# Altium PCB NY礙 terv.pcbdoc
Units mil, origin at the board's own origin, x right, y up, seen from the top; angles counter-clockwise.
Board outline 5566.92 x 3716.53 mil, 2 copper layers (Top Layer, Bottom Layer); 91 components, 103 nets, 338 pads, 72 vias.
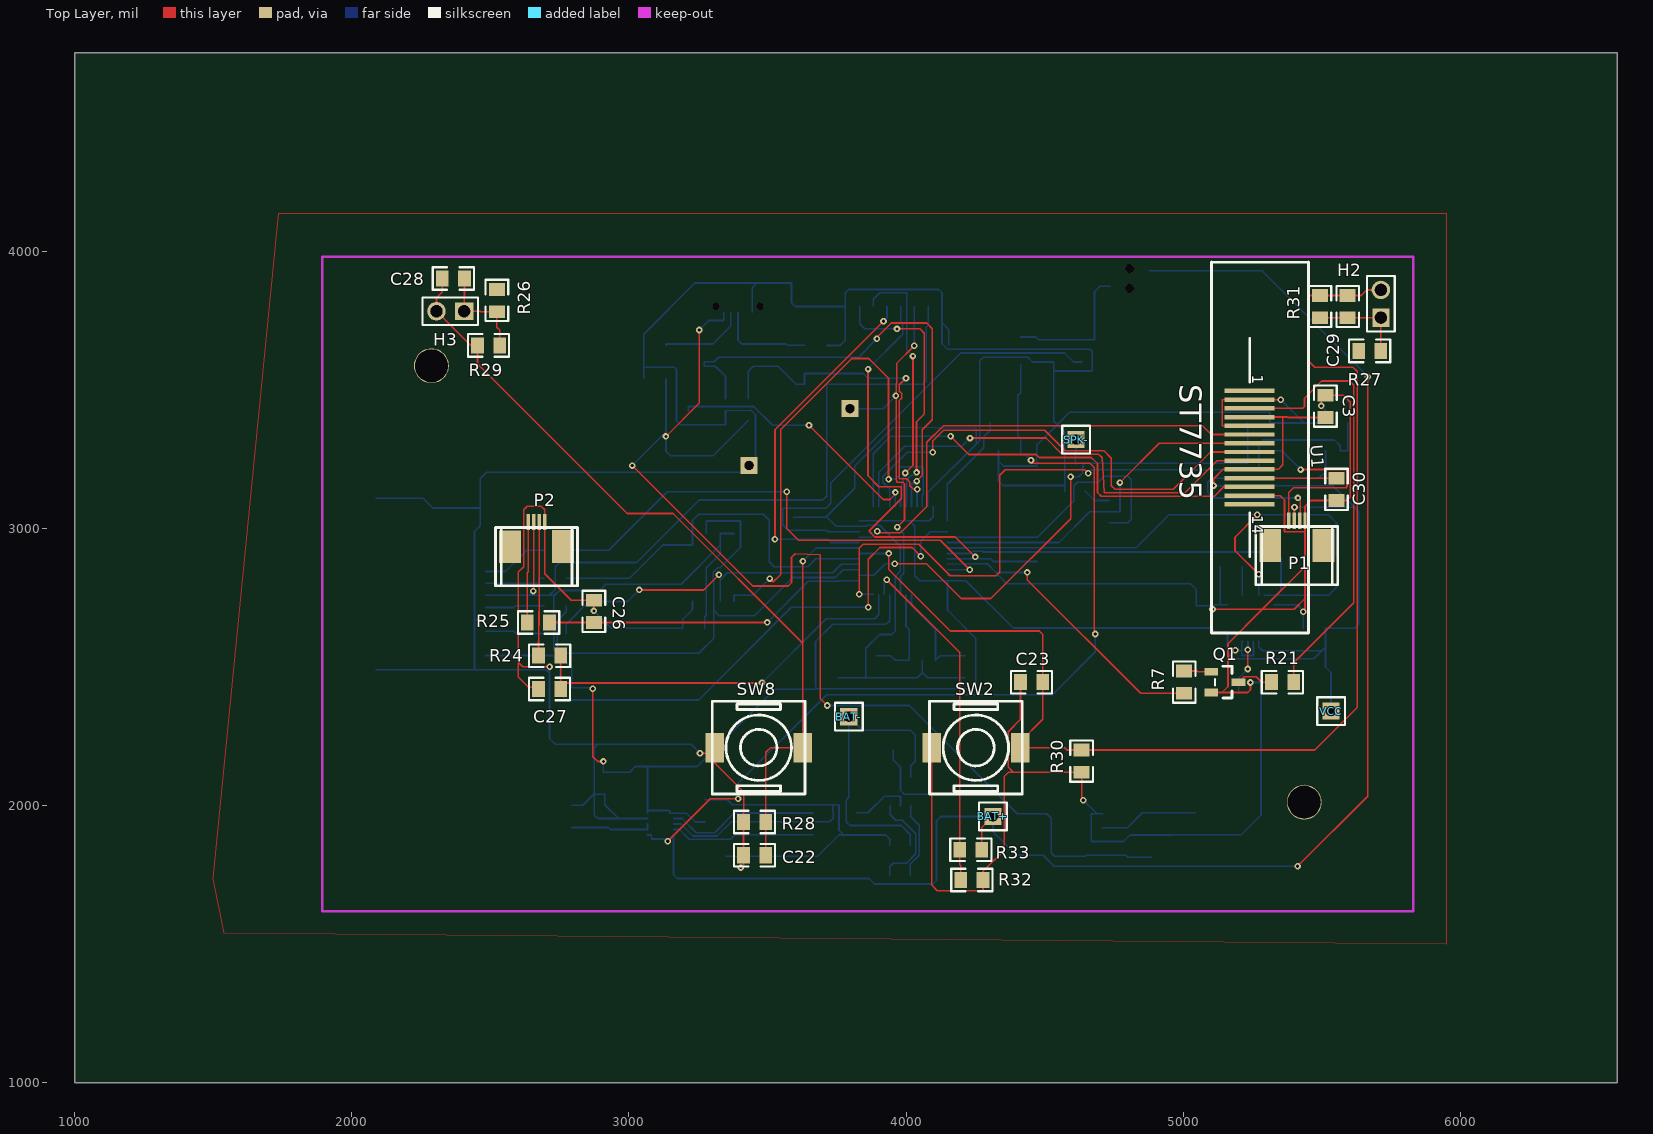
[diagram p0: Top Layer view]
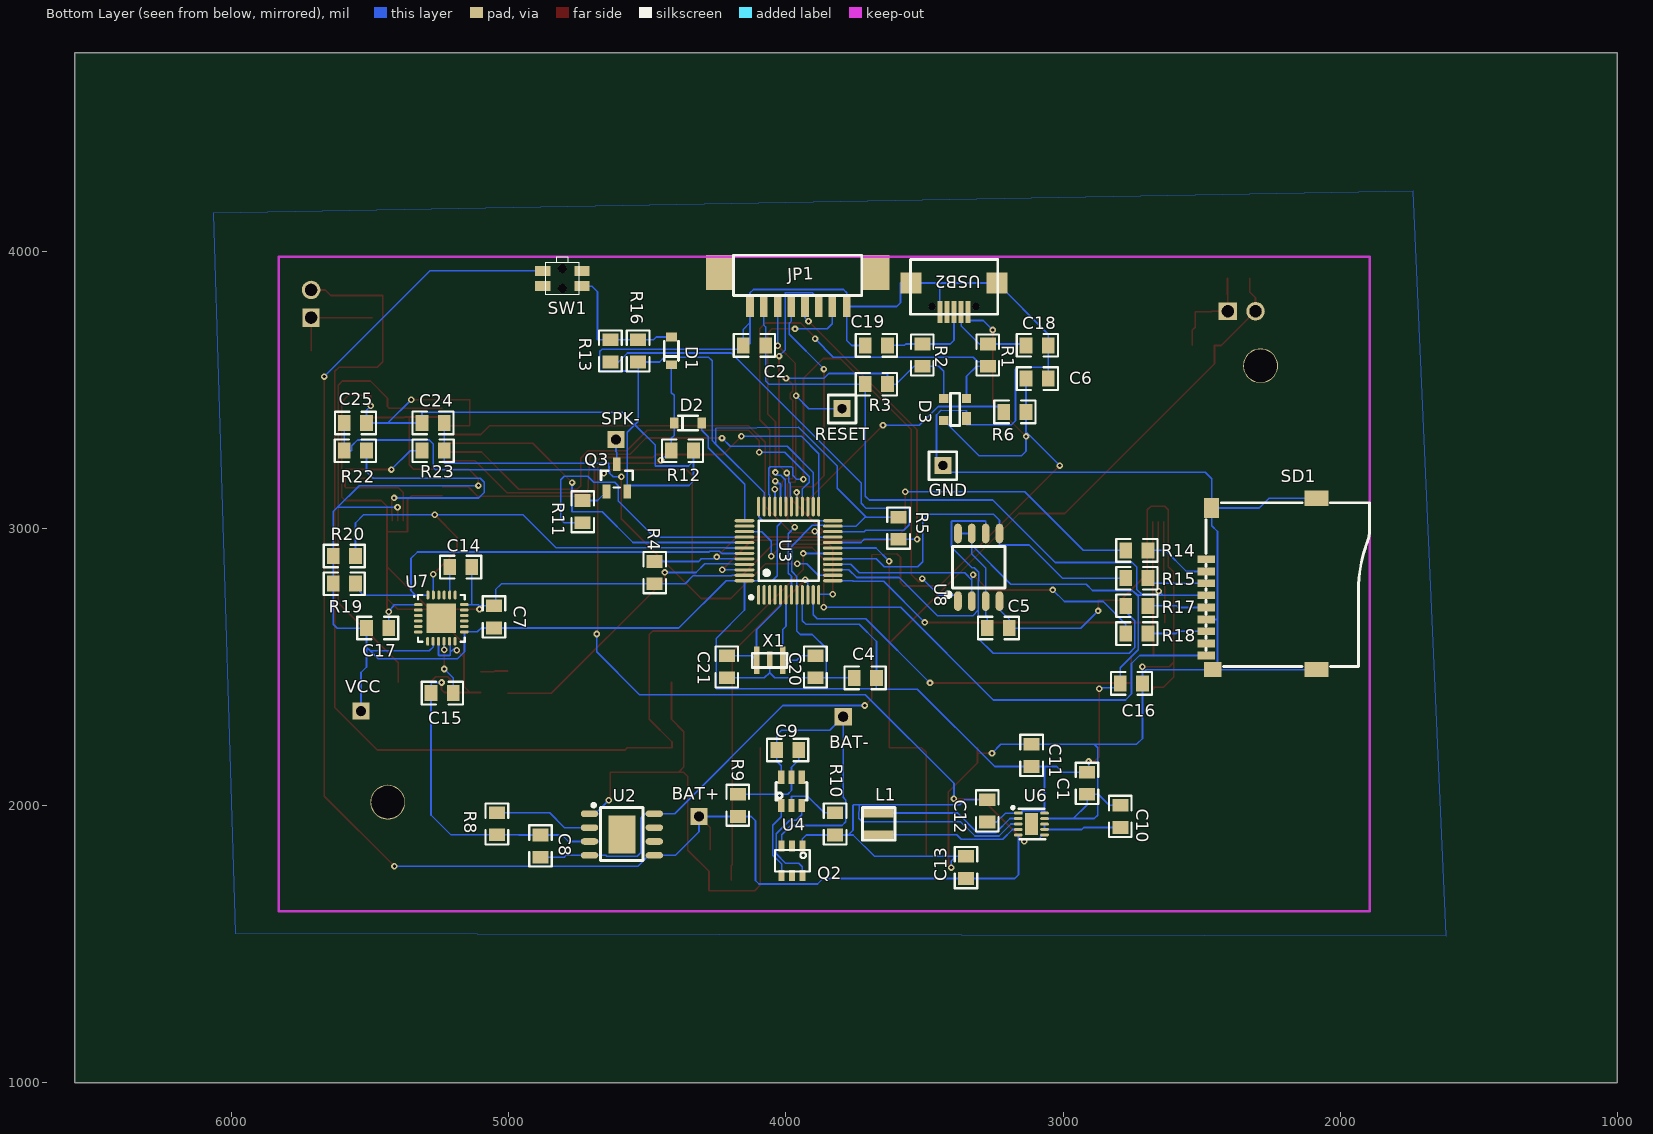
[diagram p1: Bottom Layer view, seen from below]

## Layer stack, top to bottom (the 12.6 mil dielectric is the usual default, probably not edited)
Top Layer: signal copper (thickness not stored)
Dielectric: dielectric 12.6, FR-4, Dk 4.8
Bottom Layer: signal copper (thickness not stored)

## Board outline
6566.92,1000 1000,1000 1000,4716.53 6566.92,4716.53

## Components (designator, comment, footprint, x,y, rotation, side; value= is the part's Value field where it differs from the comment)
BAT+ "Header-Male-2.54_1x1" HDR-1X1/2.54 4313.7,1960.31 r0 top
BAT- "Header-Male-2.54_1x1" HDR-1X1/2.54 3793.7,2320.31 r0 top
C1 "0.1u" 0805#1 2913.7,2040.31 r270 bottom
C2 "0.1u" 0805#1 4153.7,3660.31 r0 bottom
C3 "0.1u" 0805#2 5513.7,3480.31 r270 top
C4 "0.1u" 0805#1 3753.7,2460.31 r0 bottom
C5 "0.1u" 0805#1 3193.7,2640.31 r180 bottom
C6 "0.1u" 0805#3 3053.7,3540.31 r180 bottom
C7 "0.1u" 0805#1 5053.7,2720.31 r90 bottom
C8 "10u" 0805#1 4885.9,1893.64 r90 bottom
C9 "1u" 0805#3 4033.7,2200.31 r0 bottom
C10 "0.1u" 0805#4 2793.7,2000.31 r90 bottom
C11 "10u" 0805#1 3113.7,2220.31 r90 bottom
C12 "10u" 0805#1 3273.7,2020.31 r90 bottom
C13 "10u 10v" 0805#1 3350.4,1736.21 r270 bottom
C14 "2.2n x7r  50v" 0805#5 5213.7,2860.31 r0 bottom
C15 "0.1u x7r" 0805#1 5200.86,2405.45 r180 bottom
C16 "0.1u" 0805#1 2713.7,2440.31 r180 bottom
C17 "0.1u" 0805#1 5433.7,2640.31 r180 bottom
C18 "22p" 0805#1 3053.7,3660.31 r180 bottom
C19 "22p" 0805#3 3713.7,3660.31 r0 bottom
C20 "22p" 0805#4 3893.7,2460.31 r270 bottom
C21 "22p" 0805#1 4213.7,2460.31 r270 bottom
C22 "100n" 0805#2 3413.7,1940.31 r0 top
C23 "100n" 0805#6 4413.46,2444.82 r0 top
C24 "1u" 0805#3 5313.7,3380.31 r0 bottom
C25 "1u" 0805#3 5513.7,3380.31 r180 bottom
C26 "1u" 0805#6 2873.7,2740.31 r270 top
C27 "1u" 0805#6 2673.7,2420.31 r0 top
C28 "100n" 0805#2 2326.77,3901.57 r0 top
C29 "100n" 0805#6 5593.7,3840.31 r270 top
C30 "0.1u" 0805#2 5553.7,3180.31 r270 top
D1 "BAS70WS" SOD-323#1 4413.7,3640.31 r90 bottom
D2 "BAS70WS" SOD-323#2 4353.7,3380.31 r180 bottom
D3 "PSR05" SOT-143 3389.76,3429.13 r270 bottom
H2 "Header-Male-2.54_1x2" HDR-2X1/2.54 5713.7,3760.31 r180 top
H3 "Header-Male-2.54_1x2" HDR-2X1/2.54 2405.59,3783.4 r270 top
JP1 "1.25T-8PWT" 1.25T-8PWT 3980.39,3901.51 r0 bottom
L1 "1.5uH" 3.0*3.0*1.5MM 3665.35,1893.7 r270 bottom
P1 "FPC 0.5MM 4P" FPC-0.5MM-LSSJ-H2.0-4P 5440.94,2826.77 r0 top
P2 "FPC 0.5MM 4P" FPC-0.5MM-LSSJ-H2.0-4P 2696.93,2822.78 r0 top
Q1 "MMBTA06 1GM" SOT-23(SOT-23-3)#1 5200.65,2444.79 r270 top
Q3 "MMBTA06 1GM" SOT-23(SOT-23-3)#2 4610.31,3232.22 r0 bottom
R1 "22R" 0805#3 3271.65,3665.35 r90 bottom
R2 "22R" 0805#4 3507.87,3665.35 r90 bottom
R3 "1.5k" 0805#3 3713.7,3520.31 r0 bottom
R4 "10k" 0805#1 4473.7,2800.31 r270 bottom
R5 "10k" 0805#1 3593.7,3040.31 r90 bottom
R6 "10k" 0805#1 3213.7,3420.31 r0 bottom
R7 "1k" 0805#7 5003.74,2405.34 r90 top
R8 "2k" 0805#4 5043.38,1893.64 r270 bottom
R9 "100R" 0805#3 4173.7,2040.31 r90 bottom
R10 "2k" 0805#1 3822.91,1893.64 r270 bottom
R11 "1k" 0805#4 4733.7,3020.31 r270 bottom
R12 "10k" 0805#1 4333.7,3280.31 r180 bottom
R13 "1k" 0805#3 4633.7,3600.31 r270 bottom
R14 "1k" 0805#1 2773.7,2920.31 r0 bottom
R15 "1k" 0805#1 2773.7,2820.31 r0 bottom
R16 "10k" 0805#1 4533.7,3600.31 r270 bottom
R17 "1k" 0805#4 2773.7,2720.31 r0 bottom
R18 "1k" 0805#1 2773.7,2620.31 r0 bottom
R19 "1k5" 0805#1 5633.7,2800.31 r0 bottom
R20 "1k5" 0805#1 5633.7,2900.31 r0 bottom
R21 "100R" 0805#2 5318.7,2444.71 r0 top
R22 "1k" 0805#3 5593.7,3280.31 r0 bottom
R23 "1k" 0805#3 5233.7,3280.31 r180 bottom
R24 "1k" 0805#6 2753.7,2540.31 r180 top
R25 "1k" 0805#6 2713.7,2660.31 r180 top
R26 "1k" 0805#6 2523.7,3862.14 r270 top
R27 "1k" 0805#2 5633.7,3640.31 r0 top
R28 "10k" 0805#2 3413.7,1820.31 r0 top
R29 "10k" 0805#2 2453.7,3660.31 r0 top
R30 "10k" 0805#2 4633.7,2120.31 r90 top
R31 "10k" 0805#2 5493.7,3840.31 r270 top
R32 "10k" 0805#8 4233.7,1840.31 r180 top
R33 "20k" 0805#8 4237.9,1730.91 r0 top
SD1 "ST-TF-003A" MICRO-SD9+4P-SMD-16.1X14.5X1.85MM 2484.17,2799.27 r0 bottom
SPK- "Header-Male-2.54_1x1" HDR-1X1/2.54 4613.7,3320.31 r0 top
SW1 "SKSCLDE010" SKSCLDE010 4807.08,3901.57 r180 bottom
SW2 "SKSTAAE010" SW-SMD-8.5X8.5X3.95 4252.04,2208.66 r180 top
SW8 "SKSTAAE010" SW-SMD-8.5X8.5X3.95 3468.5,2208.66 r180 top
U1 "ST7735" "ST7735 14PIN SHORT OUTLINE" 5291.3,3291.31 r270 top
U2 "TP4056" SOP-8_EP_150MIL 4492.12,1814.96 r0 bottom
U3 "STM32F103C8T6" LQFP-48_7X7X05P 4098.5,2759.78 r270 bottom
U4 "FS312F-G" SOT23-6 3980.31,2051.18 r0 bottom
U6 "TPS63031DSKR" SON-10_3X3X05P 3114.25,1933.01 r0 bottom
U7 "MPU-6050" QFN-24_4X4X05P 5318.97,2720.41 r0 bottom
U8 "23LC1024-I/SN" SOP-8_150MIL 3229.5,2959.51 r270 bottom
USB2 "micro 5P" MICRO-USB-3 3393.7,3780.31 r270 bottom
VCC "Header-Male-2.54_1x1" HDR-1X1/2.54 5533.7,2340.31 r0 top
X1 "8MHz" 3213 4059.13,2523.56 r0 bottom

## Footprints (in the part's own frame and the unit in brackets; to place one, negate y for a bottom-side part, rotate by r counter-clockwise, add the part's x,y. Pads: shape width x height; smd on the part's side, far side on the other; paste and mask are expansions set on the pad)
1.25T-8PWT [mm]
  rect 2.4x3.2 smd: 0(-7.777,-0.552) 0(6.633,-0.551)
  rect 0.7x2 smd: 1(3.791,2.537) 2(2.542,2.537) 3(1.25,2.539) 4(0.002,2.54) 5(-1.246,2.54) 6(-2.5,2.541) 7(-3.748,2.541) 8(-5.078,2.541)
  silkscreen extent -6.45,-2.14 5.3,1.55
3.0*3.0*1.5MM [mil]
  rect 31.5x106.3 smd: 1(-0.15,0.01) 2(-78.85,0.01)
  silkscreen extent -99,-59 20,59
0805#1 [mm]
  rect 1.16x1.47 smd: 1(-0.001,0.001) 2(-2.033,0.001)
  silkscreen extent -2.89,-1.03 0.88,1.04
0805#2 [mm]
  rect 1.16x1.47 smd: 1(0.001,-0.001) 2(2.033,-0.001)
  silkscreen extent -0.88,-1.04 2.89,1.03
0805#3 [mm]
  rect 1.16x1.47 smd: 1(0.001,0.001) 2(-2.031,0.001)
  silkscreen extent -2.89,-1.03 0.88,1.04
0805#4 [mm]
  rect 1.16x1.47 smd: 1(-0.001,-0.001) 2(-2.033,-0.001)
  silkscreen extent -2.89,-1.03 0.88,1.04
0805#5 [mm]
  rect 1.16x1.47 smd: 1(0,-0.001) 2(-2.032,-0.001)
  silkscreen extent -2.89,-1.03 0.88,1.04
0805#6 [mm]
  rect 1.16x1.47 smd: 1(-0.001,0) 2(2.031,0)
  silkscreen extent -0.88,-1.04 2.89,1.03
0805#7 [mm]
  rect 1.16x1.47 smd: 1(-0.001,0.001) 2(2.031,0.001)
  silkscreen extent -0.88,-1.04 2.89,1.03
0805#8 [mm]
  rect 1.16x1.45 smd: 1(-1.016,0) 2(1.016,0)
  silkscreen extent -1.9,-1.03 1.87,1.04
3213 [mil]
  rect 19.68x98.43 smd: 1(47.22,-0.03) 3(-47.18,-0.03)
  rect 19.68x62.99 smd: 2(0.02,-0.03)
  silkscreen extent -63,-26 63,26
FPC-0.5MM-LSSJ-H2.0-4P [mm]
  rect 0.3x1.5 smd: 1(-0.021,5.082) 2(-0.52,5.082) 3(-1.02,5.082) 4(-1.52,5.082)
  rect 2x3 smd: 5(-3.206,2.822) 6(1.655,2.828)
  silkscreen extent -4.54,-0.77 2.98,4.58
HDR-1X1/2.54 [mil]
  rect 62x62 hole 35 slot 35.2 at 90 deg: 1(0,0)
  silkscreen extent -50,-50 50,50
HDR-2X1/2.54 [mil]
  rect 62x66.93 hole 43.3 slot 43.31 at 90 deg: 1(0.01,0.02)
  round 66.93 hole 43.3 slot 43.31 at 90 deg: 2(0,-100)
  silkscreen extent -50,-150 50,50
LQFP-48_7X7X05P [mm]
  oval 1.8x0.28 smd: 1(0,0) 2(0,0.5) 3(0,1) 4(0,1.5) 5(0,2) 6(0,2.5) 7(0,3) 8(0,3.5) 9(0,4) 10(0,4.5) 11(0,5) 12(0,5.5) 25(-8.1,5.5) 26(-8.1,5) 27(-8.1,4.5) 28(-8.1,4) 29(-8.1,3.5) 30(-8.1,3) 31(-8.1,2.5) 32(-8.1,2) 33(-8.1,1.5) 34(-8.1,1) 35(-8.1,0.5) 36(-8.1,0)
  oval 0.28x1.8 smd: 13(-1.3,6.8) 14(-1.8,6.8) 15(-2.3,6.8) 16(-2.8,6.8) 17(-3.3,6.8) 18(-3.8,6.8) 19(-4.3,6.8) 20(-4.8,6.8) 21(-5.3,6.8) 22(-5.8,6.8) 23(-6.3,6.8) 24(-6.8,6.8) 37(-6.8,-1.3) 38(-6.3,-1.3) 39(-5.8,-1.3) 40(-5.3,-1.3) 41(-4.8,-1.3) 42(-4.3,-1.3) 43(-3.8,-1.3) 44(-3.3,-1.3) 45(-2.8,-1.3) 46(-2.3,-1.3) 47(-1.8,-1.3) 48(-1.3,-1.3)
  silkscreen extent -6.8,-0.85 0.38,5.5
MICRO-SD9+4P-SMD-16.1X14.5X1.85MM [mil]
  rect 63x27.6 smd: 1(0.03,-89.04) 2(0.03,-45.04) 3(0.03,-2.04) 4(0.03,40.96) 5(0.03,84.96) 6(0.03,127.96) 7(0.03,170.96) 8(0.03,214.96) 9(0.03,257.96)
  rect 63x55.1 smd: G1(-23.97,309.01)
  rect 86.6x55.1 smd: G2(-397.97,309.01) G3(-397.97,-308.99)
  rect 55.1x70.9 smd: G4(-20.02,-273.99)
  silkscreen extent -591,-293 0,298
MICRO-USB-3 [mm]
  rect 1.9x1.9 smd: 0(-2.67,-3.95) 0(-2.67,3.95)
  rect 2x0.45 smd: 1(0,1.3) 2(0,0.65) 3(0,0) 4(0,-0.65) 5(0,-1.3)
  round 0.65 hole 0.65 unplated: ""(-0.521,-1.999) ""(-0.521,1.999)
  silkscreen extent -4.83,-4 0.19,4.01
QFN-24_4X4X05P [mil]
  oval 31.5x11.02 smd: 1(8,-4) 2(8,15.7) 3(8,35.4) 4(8,55) 5(8,74.7) 6(8,94.4) 13(-158,94) 14(-158,74.3) 15(-158,54.6) 16(-158,35) 17(-158,15.3) 18(-158,-4.4)
  oval 11.02x31.5 smd: 7(-26,128) 8(-45.7,128) 9(-65.4,128) 10(-85,128) 11(-104.7,128) 12(-124.4,128) 19(-125,-39) 20(-105.3,-39) 21(-85.6,-39) 22(-66,-39) 23(-46.3,-39) 24(-26.6,-39)
  rect 105.51x105.51 smd: 25(-75.02,45.01)
  silkscreen extent -160,-40 22,130
SKSCLDE010 [mil]
  rect 55.12x35.43 smd: 1(70.83,27.59) 2(-70.87,27.59) 3(70.83,-27.51) 4(-70.87,-27.51)
  round 31.5 hole 31.5 slot 31.7 at 0 deg unplated: ""(0,-35.4) ""(0,35.4)
  silkscreen extent -59,-59 59,79
SOD-323#1 [mil]
  rect 31.5x39.37 smd: 1(49.96,0.04) 2(-50.04,0.04)
  silkscreen extent -35,-26 35,26
SOD-323#2 [mil]
  rect 31.5x39.37 smd: 1(50,-0.05) 2(-50,-0.05)
  silkscreen extent -35,-26 35,26
SON-10_3X3X05P [mil]
  rect 47.24x78.74 smd: 0(-0.02,0.03)
  oval 31.5x11.02 smd: 1(47.2,-39.4) 2(47.2,-19.7) 3(47.2,0) 4(47.2,19.7) 5(47.2,39.4) 6(-47.2,39.4) 7(-47.2,19.7) 8(-47.2,0) 9(-47.2,-19.7) 10(-47.2,-39.4)
  silkscreen extent -51,-64 72,55
SOP-8_150MIL [mil]
  oval 70.87x27.56 smd: 1(222,-150) 2(222,-100) 3(222,-50) 4(222,0) 5(-22,0) 6(-22,-50) 7(-22,-100) 8(-22,-150)
  silkscreen extent 25,-193 207,20
SOP-8_EP_150MIL [mil]
  oval 62.99x23.62 smd: 1(217,-155) 2(217,-105) 3(217,-55) 4(217,-5) 5(-17,-5) 6(-17,-55) 7(-17,-105) 8(-17,-155)
  rect 98.43x137.79 smd: 9(99.99,-80.04)
  silkscreen extent 24,-192 208,14
SOT23-6 [mil]
  rect 22.2x47.7 smd: 1(36.97,51.1) 2(-0.03,51.1) 3(-37.03,51.1) 4(-37.03,-50.9) 5(-0.03,-50.9) 6(36.97,-50.9)
  silkscreen extent -56,-32 56,32
SOT-23(SOT-23-3)#1 [mil]
  rect 27.56x49.21 smd: 1(-37.42,-99.15) 2(37.38,-99.15) 3(-0.02,-0.75)
  silkscreen extent -58,-85 57,-24
SOT-23(SOT-23-3)#2 [mil]
  rect 27.56x49.21 smd: 1(37.4,99.15) 2(-37.4,99.15) 3(0,0.75)
  silkscreen extent -58,24 58,85
SOT-143 [mil]
  rect 47x33 smd: 1(31.96,41.01)
  rect 33x33 smd: 2(-39.04,41.01) 3(-39.04,-40.99) 4(39.96,-40.99)
  silkscreen extent -58,-17 58,17
"ST7735 14PIN SHORT OUTLINE" [mil]
  rect 15.75x180 smd: 1(-204.72,-51.24) 2(-173.23,-51.14) 3(-141.73,-51.25) 4(-110.24,-51.25) 5(-78.84,-51.2) 6(-47.35,-51.09) 7(-15.85,-51.21) 8(15.64,-51.2) 9(47.15,-51.2) 10(78.64,-51.09) 11(110.13,-51.21) 12(141.63,-51.2) 13(173.23,-51.15) 14(204.72,-51.24)
  silkscreen extent -670,-189 669,161
SW-SMD-8.5X8.5X3.95 [mil]
  rect 66.93x106.3 smd: 1(-159.46,0) 2(159.44,0)
  silkscreen extent -167,-167 167,167

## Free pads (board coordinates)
  rect 21.65x39.37 smd far side: 1(3941.04,1854.24) 2(3978.44,1854.24) 3(4015.84,1854.24) 4(4015.84,1747.94) 5(3978.44,1747.94) 6(3941.04,1747.94)
  round 125.98 hole 118.1 slot 118.11 at 0 deg: 319(2287.4,3586.61) 319(5437,2011.81)
  rect 62x62 hole 32 slot 32.2 at 0 deg: 320(3797.7,3432.11) 321(3433.7,3227.11)

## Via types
v1: diameter 23.62, hole 11.82, Top Layer to Bottom Layer, 72 vias

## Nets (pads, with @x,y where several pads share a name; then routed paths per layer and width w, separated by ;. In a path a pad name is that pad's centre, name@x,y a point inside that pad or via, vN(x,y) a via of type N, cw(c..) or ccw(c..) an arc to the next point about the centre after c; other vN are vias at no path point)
+5V: C6.2 C8.2 D3.4 R6.2 U2.4 U2.8 USB2.1 | length 4345
  Top Layer w6: v1(3012.2,3226.56) 3447,2791.76 3574.5,2791.76 3587,2804.26 3587,2895.76 3600,2908.76 3691,2904.26 3691,2385.76 v1(3716,2360.76) ; v1(3133.7,3331.76) 3254,3452.06 v1(3254,3715.76)
  Bottom Layer w6: v1(3012.2,3226.56) 3133.7,3348.06 ; 3133.7,3503.76 R6.2 3133.7,3348.06 ; 3133.68,3503.78 C6.2 ; v1(3254,3715.76) 3288,3749.76 3342.5,3749.76 USB2.1 ; D3.4 3303.34,3261.76 3150,3261.76 3133.7,3278.06 v1(3133.7,3331.76) 3133.7,3348.06 ; v1(3716,2360.76) 4011.2,2360.76 4402,1969.96 U2.8 4508.3,1969.96 4524,1954.26 4524,1829.26 4536.5,1816.76 4646.8,1816.76 4650,1819.96 U2.4 4794,1819.96 4800.35,1813.61 C8.2
BAT+: BAT+.1 C13.1 R9.2 R32.1 SW1.2 U2.5 U6.5 | length 5698.3
  Top Layer w6: R32.1 4273.7,1920.31 BAT+.1 ; v1(5413,1780.76) 5666,2033.76 v1(5666,3547.76)
  Bottom Layer w6: U6.5 3161,1893.61 3161,1750.22 3175,1736.22 C13.1 3866.54,1736.22 3886,1716.76 4097.5,1716.76 4110,1729.26 4110,1945.3 4125,1960.3 R9.2 4243,1960.3 BAT+.1 4313.7,1905.06 4398.8,1819.96 U2.5 4495,1819.96 4534.2,1780.76 v1(5413,1780.76) ; SW1.2 5284.6,3929.16 v1(5666,3547.76)
BAT-: BAT-.1 C9.1 pad.3 U4.6 | length 1100.8
  Bottom Layer w6: pad.3 4015.84,1894.76 3982.84,1927.76 3798,1927.76 3784,1941.76 3784,2019.76 3793.7,2029.46 BAT-.1 3842.25,2271.76 4016.21,2271.76 4033.71,2254.26 C9.1 4033.71,2159.19 4017.28,2142.76 U4.6
BATT: R32.2 R33.1 U3.10 | length 1253.4
  Top Layer w6: v1(3930.67,2814.75) 4193.7,2551.72 R32.2 4193.7,1786.96 4197.9,1782.76 R33.1
  Bottom Layer w6: U3.10 3921.33,2805.41 v1(3930.67,2814.75)
BOOT0: JP1.4 R4.2 U3.44 | length 1770.4
  Top Layer w6: v1(3863,3574.76) 3863,3189.57 3902,3150.57 3981,3150.57 3982.81,3148.76 3982.81,3107.26 3867,2991.45 3867,2989.45 3887.5,2968.95 4177.81,2968.95 v1(4250,2896.76)
  Bottom Layer w6: v1(3863,3574.76) 3988.31,3700.07 3988.31,3740.57 3980.45,3748.43 JP1.4 ; U3.44 v1@4242.94,2889.7 ; v1(4250,2896.76) v1@4242.94,2889.7 ; R4.2 4315.39,2880.31 4306,2889.7 v1@4242.94,2889.7
BOOT1: JP1.5 R5.2 U3.20 | length 1317.3
  Top Layer w6: v1(3527,2960.31) 3527,3355.41 v1(3918.85,3747.26)
  Bottom Layer w6: v1(3527,2960.31) R5.2 3718,2960.31 3729.55,2948.76 U3.20 ; v1(3918.85,3747.26) 3931.35,3759.76 JP1.5
BTN1: C23.2 C29.1 H2.2 R30.2 R31.1 SW2.1 U3.18 | length 4449
  Top Layer w6: v1(3938.03,2909.39) 3938.03,2851.76 4160.03,2629.76 4480.44,2629.76 4493.44,2616.76 C23.2 4493.44,2310.7 4411.5,2228.76 SW2.1 4411.5,2208.07 4572.33,2208.07 4580.07,2200.32 R30.2 5474.56,2200.32 5628,2353.76 5628,3566.76 5613,3581.76 5475,3581.76 5455,3601.76 5455,3839.3 5456,3840.3 R31.1 5543,3840.3 ; 5543.03,3840.33 C29.1 5643,3840.33 5662.98,3860.31 H2.2
  Bottom Layer w6: U3.18 v1(3938.03,2909.39)
BTN2: C22.2 C28.1 H3.2 R28.2 R29.1 SW8.1 U3.19 | length 3393.2
  Top Layer w6: C28.1 2326.81,3852.98 2305.59,3831.76 H3.2 2429.23,3659.76 R29.1@2453.71,3659.76 ; R29.1 R29.1@2453.71,3659.76 ; R28.2 3493.71,1879.76 ; 3493.74,1879.79 C22.2 3493.74,2191.76 3510.74,2208.76 SW8.1@3627.95,2208.76 ; SW8.1 SW8.1@3627.95,2208.76 ; v1(3627.95,2881.71) 3627.95,2584.81 ; R29.1@2453.71,3659.76 2453.71,3593.76 2993.71,3053.76 3159,3053.76 3627.95,2584.81 ; SW8.1@3627.95,2208.76 3627.95,2584.81
  Bottom Layer w6: v1(3627.95,2881.71) 3675.31,2929.07 U3.19
C10_2: C10.2 U6.7 U6.8 | length 296
  Bottom Layer w6: C10.2 2926,1920.27 2932.96,1913.31 U6.7 U6.8
C28_2: C28.2 H3.1 R26.2 R29.2 | length 363.3
  Top Layer w6: C28.2 2406.81,3842.97 2405.6,3841.76 H3.1 2464,3783.41 2465.26,3782.15 R26.2 2523.69,3725.78 2533.71,3715.76 R29.2
C29_2: C29.2 H2.1 R27.2 R31.2 | length 340
  Top Layer w6: R31.2 5543,3760.3 ; 5543.03,3760.33 C29.2 5653,3760.33 5653.04,3760.29 H2.1 5713.69,3699.79 ; R27.2 5713.72,3699.76
CPOUT: C14.1 U7.20 | length 100.9
  Bottom Layer w6: U7.20 5213.67,2810.41 5213.71,2810.45 C14.1
D+: D3.3 R2.2 R3.2 U3.33 | length 1276.5
  Top Layer w6: v1(4000.01,3541.76) 3976.19,3517.93 3976.19,3495.06 3984.51,3486.73 3984.51,3469.49 3976.19,3461.17 3976.19,3180.76 3978,3178.95 4002.44,3178.95 4013.82,3167.56 4013.82,3154.26 4027.32,3140.76 v1(4040.62,3140.76)
  Bottom Layer w6: D3.3 3430.75,3566.76 3449.3,3585.31 R2.2 3538,3585.31 3603.04,3520.27 R3.2 3633.71,3557.76 3634.71,3558.76 3846,3558.76 3863,3541.76 v1(4000.01,3541.76) ; U3.33 4039.44,3139.58 v1(4040.62,3140.76)
D-: D3.2 R1.2 U3.32 | length 1764.6
  Top Layer w6: v1(3895,3683.76) 3895,3688.76 3947,3740.76 4075,3740.76 4095,3720.76 4095,3391.76 4059,3355.76 4059,3190.76 v1(4039,3170.76)
  Bottom Layer w6: D3.2 3348.75,3548.62 3312,3585.37 R1.2 3271.65,3601.76 3308,3601.76 3324,3617.76 3829,3617.76 v1(3895,3683.76) ; U3.32 4019.76,3160.76 4020.76,3161.76 4038,3161.76 4039,3162.76 v1(4039,3170.76)
D_BR: R7.1 U3.45 | length 1063.5
  Top Layer w6: v1(4438,2840.76) 4438,2813.88 4846.57,2405.31 R7.1
  Bottom Layer w6: U3.45 4205.74,2872.76 4293,2872.76 4325,2840.76 v1(4438,2840.76)
D_CS: U1.12 U3.25 | length 1740
  Top Layer w6: v1(4160.7,3332.06) 4226.19,3266.57 4470.13,3266.57 4480.95,3255.76 4669,3255.76 4690.81,3233.95 4690.81,3129.26 4704.31,3115.76 5113.12,3115.76 5147.05,3149.68 U1.12
  Bottom Layer w6: U3.25 3881.96,3269.72 3944.3,3332.06 v1(4160.7,3332.06)
D_DC: U1.7 U3.41 | length 1299.7
  Top Layer w6: v1(4772,3165.26) 4913.9,3307.16 U1.7
  Bottom Layer w6: U3.41 4552,2948.76 4663,3059.76 4772,3060.76 v1(4772,3165.26)
D_RS: U1.6 U3.21 | length 1730.1
  Top Layer w6: v1(3896.5,2989.76) 3902.31,2983.95 3980.19,2983.95 4074.81,3078.57 4074.81,3310.57 4135,3370.76 5070,3370.76 5102.1,3338.66 U1.6
  Bottom Layer w6: U3.21 3875.18,2968.44 v1(3896.5,2989.76)
GND: C1.1 C2.1 C3.1 C4.1 C5.1 C6.1 C7.1 C8.1 C10.1 C11.1 C12.1 C13.2 C14.2 C15.2 C16.1 C17.1 C18.1 C19.1 C20.1 C21.1 C22.1 C23.1 C24.1 C25.1 C26.1 C27.1 C30.2 D3.1 JP1.1 JP1.8 P1.1 P2.1 pad.1 pad.321 Q1.2 Q3.2 R4.1 R5.1 R8.1 R10.1 R12.1 R16.1 R28.1 R30.1 R33.2 SD1.6 SD1.G1 SD1.G2 SD1.G3 SD1.G4 SW2.2 SW8.2 U1.2 U1.5 U1.13 U2.1 U2.3 U3.8 U3.23 U3.35 U3.47 U6.3 U6.9 U7.1 U7.9 U7.11 U7.18 U8.4 USB2.0 USB2.5 X1.2 | length 25650.5
  Top Layer w6: C27.1 2673.68,2426.76 2637.5,2426.76 2601,2463.26 2601,2516.76 ; v1(2713.7,2500.76) 2617,2500.76 2601,2516.76 ; v1(2873.7,2702.06) C26.1 2791.53,2740.33 2696.1,2835.76 P2.1 2696.1,3066.76 2683.1,3079.76 2633,3079.76 2620,3066.76 2620,2861.76 2601,2842.76 2601,2516.76 ; v1(3256.55,2188.76) SW8.2@3309.05,2188.76 ; SW8.2 SW8.2@3309.05,2188.76 ; v1(3404,1775.76) 3413.71,1785.47 R28.1 3413.71,1879.76 ; 3413.74,1879.79 C22.1 3414.81,2004.02 3414.81,2048.69 3309.05,2154.45 SW8.2@3309.05,2188.76 ; SW2.2 4092.6,1712.66 4112.5,1692.76 4276.9,1692.76 4277.9,1693.76 R33.2 4277.9,1762.66 4354,1838.76 4354,2104.26 4370.06,2120.32 4387.5,2120.32 ; C23.1 4413.44,2310.76 4369,2266.32 4369,2138.82 4387.5,2120.32 ; v1(4640,2018.96) 4633.71,2025.25 R30.1 4387.5,2120.32 ; Q1.2 5140.15,2407.41 ; v1(5106,2707.76) 5286.1,2707.76 ; v1(5188,2559.76) 5162,2533.76 ; U1.5 5142,3370.15 5141,3371.15 5141,3463.54 5142,3464.54 U1.2 v1(5352.72,3464.54) ; U1.13 5350.18,3118.08 5366,3102.26 5366,2988.76 5367,2987.76 5439.1,2987.76 5440.1,2988.76 ; v1(5243,2443.76) 5243,2417.41 5233,2407.41 5140.15,2407.41 ; v1(5433.71,2698.76) 5440.1,2705.15 5440.1,2746.86 ; v1(5498,3441.76) 5498,3480.27 C3.1 5578.49,3480.27 5603.63,3455.13 5603.63,3112.93 5591,3100.3 C30.2 5461.14,3100.3 5440.1,3079.26 P1.1 5440.1,2988.76 ; 5140.15,2407.41 5162,2429.26 5162,2533.76 ; 5162,2533.76 5162,2583.66 5286.1,2707.76 ; 5286.1,2707.76 5440.1,2861.76 ; 5286.1,2707.76 5401,2707.76 5440.1,2746.86 ; 5440.1,2746.86 5440.1,2861.76 ; 5440.1,2861.76 5440.1,2988.76
  Bottom Layer w6: SD1.G2 SD1.G1@2443,2490.26 ; SD1.G3 2257,3108.26 2292,3073.26 SD1.G4 ; SD1.6 2444,2671.31 ; v1(2713.7,2500.76) 2713.7,2476.56 ; C10.1 2833,2000.27 2873.08,2040.35 2875,2040.35 ; v1(2873.7,2702.06) 2936,2639.76 3193.74,2639.76 C5.1 3193.74,2670.76 3229.5,2706.52 U8.4 ; C1.1 C1.1@2913,2040.35 ; C6.1 3053.68,3579.76 ; U6.9 2963,1952.71 ; U6.3@3161.45,1933.06 3187.92,1933.06 3231.18,1889.76 3318,1889.76 3370,1941.76 3724.5,1941.76 3737,1954.26 3736,2002.76 ; v1(3256.55,2188.76) 3225,2220.31 C11.1 2887.5,2220.31 ; C12.1 3355.37,2020.31 3372.9,2002.79 3736,2002.79 3755.97,2002.79 3758,2000.76 3758,1910.64 3775,1893.64 ; C13.2 3387.5,1816.22 ; v1(3404,1775.76) 3404,1799.72 3387.5,1816.22 ; USB2.5 3444.9,3867.83 3462.5,3885.43 ; R5.1 3710.55,3040.31 ; C19.1 3713.71,3659.76 3762.5,3659.76 3780.45,3677.71 JP1.8@3780.45,3800.76 ; C4.1 3823,2460.27 3823.06,2460.33 C20.1 ; pad.1 3941.04,1879.26 3926.66,1893.64 R10.1 3775,1893.64 ; X1.2 4059.15,2479.26 ; U3.35 4078.81,3129.5 4252.95,3303.64 ; U3.47 4195.11,2830.65 4197,2828.76 4335.55,2828.76 4364,2800.31 R4.1 5026.95,2800.31 5048,2779.26 5048,2720.27 C7.1 5093.49,2720.27 ; C2.1 4153.66,3718.76 4129.65,3742.77 ; C21.1 4078.08,2460.33 4059.15,2479.26 ; R12.1 4333.7,3242.76 ; Q3.2 Q3.2@4572.91,3154.76 ; v1(4640,2018.96) U2.1@4689,1969.96 ; U2.1 U2.1@4689,1969.96 ; v1(5106,2707.76) 5093.49,2720.27 ; C14.2 5133.71,2726.1 5135,2724.81 ; U7.18 5135,2724.81 ; v1(5188,2559.76) 5195,2566.76 5211.95,2553.78 ; U7.11 5214.27,2591.9 5211.95,2591.9 5211.95,2553.78 ; v1(5243,2443.76) 5279.86,2443.76 C15.2 5280.86,1965.53 5209,1893.67 R8.1 4964.06,1893.67 4964,1893.61 C8.1 4808.65,1893.61 4785,1869.96 U2.3 4669,1869.96 4668,1870.96 4668,1968.96 4669,1969.96 U2.1@4689,1969.96 ; U7.9 5253.57,2582.67 5253.81,2582.42 5253.81,2542.76 5252,2540.95 5213,2540.95 5211.95,2542 5211.95,2553.78 ; U7.1 5413.56,2724.41 v1(5433.71,2698.76) C17.1 ; v1(5352.72,3464.54) 5436.95,3380.31 ; v1(5498,3441.76) 5513.68,3426.08 C25.1 5436.95,3380.31 ; SD1.G1@2443,2490.26 SD1.G1 2700,2490.26 2713.7,2476.56 ; SD1.G1@2443,2490.26 2443,2670.31 2444,2671.31 ; 2444,2671.31 2443,2672.31 2443,2988.76 2464.15,3009.91 SD1.G4 ; SD1.G4 2464.15,3179.41 2487.5,3202.76 3416,3202.76 3457,3243.76 3457,3409.26 3440.5,3425.76 3348.75,3424.76 D3.1 3348.75,3373.26 3187.5,3373.26 3172,3388.76 3172,3573.76 3165,3580.76 3054.68,3580.76 3053.68,3579.76 ; 2713.7,2476.56 C16.1 2713.7,2241.76 2735.15,2220.31 2887.5,2220.31 ; 2875,2040.35 C1.1@2913,2040.35 ; 2875,2040.35 2875,2207.81 2887.5,2220.31 ; 2875,2040.35 2875,1965.21 2887.5,1952.71 2963,1952.71 ; C1.1@2913,2040.35 2913,2002.71 2963,1952.71 ; 3053.68,3579.76 3053.68,3599.76 C18.1 3053.69,3700.93 3238.19,3885.43 3462.5,3885.43 ; 3387.5,1816.22 3680.46,1816.22 3757.88,1893.64 3775,1893.64 ; 3462.5,3885.43 3549.21,3885.43 3587,3885.43 3587,3813.76 3600,3800.76 JP1.8@3780.45,3800.76 ; 3710.55,3040.31 3715,3040.31 3747.5,3007.81 U3.23 3857.07,3007.81 3860.13,3010.87 3904.84,3010.87 3979.81,2935.9 3979.81,2845.58 3960.7,2826.47 U3.8 3960.7,2629.26 3948.2,2616.76 3905,2616.76 3855,2566.76 3855,2461.33 C20.1 ; 3710.55,3040.31 3815,3144.76 3815,3224.76 3955,3364.76 4252.95,3361.81 4252.95,3303.64 ; JP1.8@3780.45,3800.76 JP1.8 3780.45,3849.76 3792.57,3861.88 4117.53,3861.88 4129.65,3849.76 JP1.1 4129.65,3742.77 ; C20.1 4040.22,2460.33 4059.15,2479.26 ; 4129.65,3742.77 4129.65,3666.76 4149.65,3646.76 4664,3646.76 4672,3638.76 4672,3568.76 4671,3567.76 4534.65,3567.76 4533.65,3568.76 ; 4252.95,3303.64 4266,3316.69 4266.07,3604.26 4279.57,3617.76 4439,3617.76 4456.46,3600.3 R16.1 4533.65,3568.76 ; 4333.7,3242.76 4351.75,3224.71 4471.11,3224.71 4472.16,3225.76 4472.16,3300.92 4545.46,3374.22 ; 4333.7,3242.76 4333.7,3171.06 4350,3154.76 Q3.2@4572.91,3154.76 ; 4533.65,3568.76 4533.65,3386.02 4545.46,3374.22 ; 4545.46,3374.22 4590,3418.76 5312.71,3418.76 5313.71,3417.76 C24.1 5413.01,3380.31 5436.95,3380.31 ; 4545.46,3374.22 4572.91,3346.76 Q3.2@4572.91,3154.76 ; 5093.49,2720.27 5105,2720.27 5109.54,2724.81 5135,2724.81
LED-: R21.2 U1.3 | length 1602.9
  Top Layer w6: U1.3 5431.42,3433.04 5437.77,3439.39 5437.77,3469.82 5499.72,3531.76 5601,3531.76 5616,3516.76 5616,2731.76 5398.7,2514.46 R21.2
MISO1: R18.1 U3.16 U8.2 | length 1280.9
  Top Layer w6: v1(3037,2777.76) 3270,2777.76 v1(3325,2832.76)
  Bottom Layer w6: R18.1 2773.69,2654.26 2855.19,2735.76 2995,2735.76 v1(3037,2777.76) ; v1(3325,2832.76) 3329.5,2828.26 3329.5,2813.76 ; U8.2 3329.5,2813.76 ; U3.16 3766.26,2870.02 3735.81,2839.57 3355.31,2839.57 3329.5,2813.76
MISO2: U3.27
MOSI1: R15.1 U3.17 U8.5 | length 1383.6
  Bottom Layer w6: R15.1 2773.69,2819.76 3002,2819.76 3122,2939.76 3228.5,2939.76 3229.5,2940.76 U8.5 3229.5,3029.26 3251,3050.76 3484.5,3050.76 3506,3029.26 3506,2879.26 3524.36,2860.9 3645,2860.9 3673.81,2889.7 U3.17
MOSI2: U1.8 U3.28 | length 1737.2
  Top Layer w6: v1(4097,3274.76) 4097,3315.49 4135.27,3353.76 4500.7,3353.76 4574.7,3279.76 4714.19,3279.76 4740.69,3253.26 4740.69,3154.26 4754.19,3140.76 4964.09,3140.76 5099,3275.67 U1.8
  Bottom Layer w6: U3.28 3941.02,3141.76 3916.19,3166.59 3916.19,3186.37 4004.58,3274.76 v1(4097,3274.76)
OSC_IN: C21.2 U3.5 X1.1 | length 386.3
  Bottom Layer w6: U3.5 4019.76,2721 4106.35,2634.41 X1.1 4123.09,2540.33 C21.2
OSC_OUT: C20.2 U3.6 X1.3 | length 366.3
  Bottom Layer w6: C20.2 3944,2540.33 3960.74,2523.59 X1.3 4011.95,2634.76 4000.07,2646.64 U3.6
P1_2: P1.2 R22.2 | length 976
  Top Layer w6: v1(5414.5,3109.76) 5422.81,3101.45 5422.81,3052.67 5420.45,3052.67 P1.2
  Bottom Layer w6: v1(5414.5,3109.76) 5108.5,3109.76 5089,3129.26 5089,3166.76 5103,3180.76 5490,3180.76 5513.72,3204.48 R22.2
P1_4: P1.4 R23.2 | length 689.5
  Top Layer w6: P1.4 5381.1,3129.26 5398.6,3146.76 5588.63,3146.76 5591.63,3149.76 5591.63,3210.76 5590.25,3212.14 v1(5424,3212.14)
  Bottom Layer w6: R23.2 5313.68,3279.76 5356.38,3279.76 v1(5424,3212.14)
P2_2: P2.2 R24.2 | length 482.6
  Top Layer w6: R24.2 2676.45,2755.68 P2.2
P2_4: P2.4 R25.2 | length 364
  Top Layer w6: R25.2 2633.72,2839.76 2637.1,2843.14 P2.4
PS_BTN: D1.1 R13.2 R16.2 SW1.3 | length 508.2
  Bottom Layer w6: D1.1 4468,3690.27 4477.97,3680.3 R16.2 4583,3680.3 R13.2 4679,3680.31 4680,3681.31 4680,3854.26 4699.8,3874.06 SW1.3
PS_EN: D1.2 D2.2 R12.2 U6.6 | length 3239
  Top Layer w6: v1(3140,1870.76) 3293,2023.76 v1(3394,2023.76) ; v1(4451,3245.76) 4451,3235.76 4663.81,3234.76 4678.81,3219.76 4678.81,2622.95 v1(4683,2618.76)
  Bottom Layer w6: U6.6 3081,1893.61 3082,1878.76 3132,1878.76 v1(3140,1870.76) ; v1(3394,2023.76) 3394,2080.26 3713.5,2399.76 4528.5,2399.76 4683,2554.26 v1(4683,2618.76) ; D1.2 4413.74,3489.8 4403.7,3479.76 D2.2 4403.7,3334.76 4413.7,3324.76 R12.2 4413.7,3265.76 4431,3265.76 v1(4451,3245.76)
PS_ENB: D2.1 U3.37 | length 417.5
  Bottom Layer w6: U3.37 4149,3027.5 4149,3159.41 4280.34,3290.75 4280.34,3330.27 4303.7,3353.63 D2.1
Q1_1: Q1.1 R7.2 | length 99.1
  Top Layer w6: R7.2 5051,2485.31 5054.1,2482.21 Q1.1
Q1_3: Q1.3 R21.1 | length 135.2
  Top Layer w6: Q1.3 5200.86,2444.81 5220.62,2464.57 5263.81,2464.57 5283.67,2444.71 R21.1
Q2_2: pad.2
Q2_5: pad.5
Q3_1: Q3.1 R11.2 | length 99.6
  Bottom Layer w6: Q3.1 4680.43,3100.35 R11.2
R26_1: R26.1
R27_1: R27.1
RAM_CS: U3.34 U8.1 | length 1945.6
  Top Layer w6: v1(3508,2818.76) 3508,2817.76 3519,2806.76 3521,2806.76 3548,2833.76 3548,3356.76 3804,3612.76 3866,3612.76 3937,3541.76 v1(3937,3177.07)
  Bottom Layer w6: U8.1 3379.5,2758.76 3448,2758.76 v1(3508,2818.76) ; v1(3937,3177.07) 3962,3177.07 3976.19,3191.26 3976.19,3218.76 3980,3222.57 4056.5,3222.57 4062.31,3216.76 4062.31,3123.13 4059.13,3119.95 U3.34
REGOUT: C15.1 U7.10 | length 200.7
  Top Layer w6: v1(5233,2492.4) v1(5233,2561.76)
  Bottom Layer w6: C15.1 5200.86,2460.26 v1(5233,2492.4) ; v1(5233,2561.76) 5233.97,2562.73 U7.10
RESET: JP1.3 pad.320 U3.7 | length 1305
  Top Layer w6: v1(3968,3004.76) 3994.81,3031.57 3994.81,3159.88 3987.75,3166.95 3966,3166.95 3966,3173.98 3964.19,3175.79 3964.19,3522.9 3966,3524.72 3966,3595.16 v1(4029.6,3658.76)
  Bottom Layer w6: pad.320 3917.7,3432.11 v1(3963.7,3478.11) ; v1(3968,3004.76) 3991.81,2980.95 3991.81,2838.45 3980.39,2827.03 U3.7 ; v1(4029.6,3658.76) JP1.3
RX0: JP1.7 U3.31 | length 972.7
  Top Layer w6: v1(3967.5,3719.76) 4050.5,3719.76 4066,3704.26 4066,3412.76 4038,3384.76 v1(4038,3201.76)
  Bottom Layer w6: JP1.7 3832.85,3737.91 3851,3719.76 v1(3967.5,3719.76) ; U3.31 4003,3111.69 4003,3175.76 4018.81,3191.57 4038,3192.57 v1(4038,3201.76)
SCK1: R17.1 U3.15 U8.6 | length 2004
  Bottom Layer w6: R17.1 2773.69,2699.45 2741,2666.76 2741,2569.76 2761.86,2548.9 3252.14,2548.9 3306,2602.76 3306,2705.57 ; U8.6 3279.5,3025.76 3280.5,3026.76 3401.5,3026.76 3402.5,3025.76 3402.5,2931.26 3329.08,2857.84 3320.27,2857.84 3304.19,2841.76 3304.19,2813.76 ; U3.15 3773,2850.33 3745.03,2822.36 3591,2822.36 3453.4,2684.76 3325,2684.76 3306,2705.57 ; 3304.19,2813.76 3306,2811.95 ; 3304.19,2813.76 3304.19,2811.95 3306,2811.95 ; 3306,2705.57 3306,2811.95
SCK2: U1.9 U3.26 | length 1707.9
  Top Layer w6: v1(4231,3325.76) 4505,3325.76 4563,3267.76 4694.5,3267.76 4708,3254.26 4716,3128.76 5006.6,3128.76 5122,3244.16 U1.9
  Bottom Layer w6: U3.26 3901.65,3201.49 3995.92,3295.76 4201,3295.76 v1(4231,3325.76)
SCL: R20.2 U3.42 U7.23 | length 1942.9
  Top Layer w6: v1(5268,3048.76) 5187.5,2968.26 5187.5,2919.26 v1(5272.67,2834.09)
  Bottom Layer w6: U3.42 4216.61,2929.07 4217.24,2929.71 4829.95,2929.71 4949,3048.76 v1(5268,3048.76) 5524.4,3048.76 5553.7,3019.46 R20.2 ; U7.23 v1(5272.67,2834.09)
SD1_1: SD1.1
SD1_2: R14.2 SD1.2 | length 241.6
  Bottom Layer w6: SD1.2 2555,2844.31 2631.45,2920.76 2693.67,2920.76 R14.2
SD1_3: R15.2 SD1.3 | length 228.5
  Bottom Layer w6: SD1.3 2675.34,2801.31 2675.34,2820.31 R15.2
SD1_5: R17.2 SD1.5 | length 212
  Bottom Layer w6: SD1.5 2585,2714.31 2591.04,2720.35 R17.2
SD1_7: R18.2 SD1.7 | length 212.8
  Bottom Layer w6: SD1.7 2584,2628.31 2592.02,2620.29 R18.2
SD1_8: SD1.8
SD_CS: R14.1 U3.46 | length 1818.7
  Top Layer w6: v1(3570,3131.76) 3570,2999.26 3612.31,2956.95 4123.39,2956.95 v1(4230,2850.33)
  Bottom Layer w6: R14.1 2773.67,2920.76 2927,2920.76 3138,3131.76 v1(3570,3131.76) ; U3.46 v1(4230,2850.33)
SD_SENSE: SD1.9 U3.39 | length 2206.9
  Top Layer w6: v1(3864,2714.76) 3864,2888.76 3906,2930.76 4022,2930.76 v1(4053,2899.76)
  Bottom Layer w6: SD1.9 2724,2541.31 2753,2512.31 2753,2402.76 2775,2380.76 3252,2380.76 3586,2714.76 v1(3864,2714.76) ; v1(4053,2899.76) 4053,2953.63 4087.5,2988.13 U3.39
SDA: R19.2 U3.43 U7.24 | length 1643.5
  Bottom Layer w6: U3.43 4232,2909.39 4240.31,2917.71 4275,2917.71 4277.95,2914.76 5330,2914.76 5353,2891.76 5353,2774.26 5337.5,2758.76 ; U7.24 5292.37,2758.76 5337.5,2758.76 ; R19.2 5553.69,2787.76 5524.69,2758.76 5337.5,2758.76
SPK-: Q3.3 SPK-.1 | length 90.2
  Bottom Layer w6: Q3.3 4610.31,3273.76 4613.7,3277.15 SPK-.1
SPKR: R11.1 U3.40 | length 1017.7
  Bottom Layer w6: U3.40 4474.68,2968.44 4605,3098.76 4605,3154.26 4617.5,3166.76 4694,3166.76 4715,3187.76 4800,3187.76 4812.5,3175.26 4812.5,3032.85 4800,3020.35 R11.1
SW1_1: SW1.1
SW1_4: SW1.4
TX0: JP1.6 U3.30 | length 957.9
  Top Layer w6: v1(3997,3199.76) 4025,3227.76 v1(4025,3621.76)
  Bottom Layer w6: JP1.6 3881.95,3826.76 3905.07,3849.88 4002.11,3849.88 4003.23,3848.76 4003.23,3643.53 v1(4025,3621.76) ; U3.30 3980.39,3108.76 3985,3113.37 3985,3162.76 3989.63,3167.39 3989.63,3198.76 3990.63,3199.76 v1(3997,3199.76)
U1_1: U1.1
U1_11: C30.1 U1.11 | length 314
  Top Layer w6: U1.11 5396,3181.18 5396.88,3180.3 C30.1
U1_14: U1.14
U2_2: R8.2 U2.2 | length 356.5
  Bottom Layer w6: U2.2 4799,1919.96 4852.71,1973.67 R8.2
U2_6: U2.6
U2_7: U2.7
U3_1: U3.1
U3_2: U3.2
U3_3: U3.3
U3_4: U3.4
U3_22: R13.1 U3.22 | length 1712.6
  Bottom Layer w6: U3.22 3717.63,2988.13 3713,2992.76 3575,2992.76 3555,3012.76 3555,3071.76 3556,3072.76 3711.5,3072.76 3729,3090.26 3729,3163.76 4198,3632.76 4572,3632.76 4604.45,3600.31 R13.1
U3_38: U3.38
U4_1: pad.4 U4.1 | length 277.9
  Bottom Layer w6: pad.4 4015.84,1788.76 4047.67,1820.59 4047.67,1928.35 4017.28,1958.74 U4.1
U4_2: R10.2 U4.2 | length 215
  Bottom Layer w6: R10.2 3862.5,1973.64 3922.62,2033.76 3980.28,2032.76 U4.2
U4_3: pad.6 U4.3 | length 372.2
  Bottom Layer w6: pad.6 3941.04,1779.26 3953.54,1791.76 4001.67,1791.76 4035.67,1825.76 4035.67,1898.09 3987,1946.76 3962.5,1946.76 3943.28,1965.98 U4.3
U4_4: U4.4
U4_5: C9.2 R9.1 U4.5 | length 356.3
  Bottom Layer w6: C9.2 3953.71,2164.33 3980.28,2137.76 U4.5 3980.28,2054.26 3994.24,2040.3 R9.1
U6_2: L1.2 U6.2 | length 554.3
  Bottom Layer w6: U6.2 3191.76,1952.66 3242.72,1901.76 3309.28,1901.76 3380.08,1972.56 L1.2
U6_4: L1.1 U6.4 | length 525.3
  Bottom Layer w6: U6.4@3161.45,1913.36 3182.34,1913.36 3217.9,1877.76 3367.48,1877.76 3383.59,1893.86 L1.1@3665.34,1893.86
U7_2: U7.2
U7_3: U7.3
U7_4: U7.4
U7_5: U7.5
U7_6: U7.6
U7_7: U7.7
U7_12: U7.12
U7_14: U7.14
U7_15: U7.15
U7_16: U7.16
U7_17: U7.17
U7_19: U7.19
U7_21: U7.21
U7_22: U7.22
USB2_2: C18.2 R1.1 USB2.2 | length 316.3
  Bottom Layer w6: C18.2 3133.69,3665.37 R1.1 3303,3665.37 3368.1,3730.47 USB2.2
USB2_3: C19.2 R2.1 USB2.3 | length 348.9
  Bottom Layer w6: USB2.3 3393.7,3679.26 3407.65,3665.31 R2.1 3568,3665.31 3572.99,3660.32 C19.2
USB2_4: USB2.4
USB_SENSE: R6.1 U3.29 | length 972.2
  Top Layer w6: v1(3650,3371.76) 3917.5,3104.26 3942.12,3104.26 3962,3124.14 v1(3962,3129.76)
  Bottom Layer w6: R6.1 3213.7,3439.76 3451,3439.76 3519,3371.76 v1(3650,3371.76) ; U3.29 3960.7,3128.46 v1(3962,3129.76)
VCC: C1.2 C2.2 C3.2 C4.2 C5.2 C7.2 C11.2 C12.2 C16.2 C17.2 JP1.2 P1.3 P2.3 R3.1 R19.1 R20.1 SD1.4 U1.4 U1.10 U3.9 U3.24 U3.36 U3.48 U6.1 U6.10 U7.8 U7.13 U8.3 U8.7 U8.8 VCC.1 | length 13032.8
  Top Layer w6: v1(2655,2773.76) 2656.8,2775.56 P2.3 ; v1(2870,2420.76) 2870,2176.26 2887.5,2158.76 v1(2908,2158.76) ; v1(5110,3154.26) 5110,3179.26 5143.41,3212.67 U1.10 5343.41,3212.67 5360,3229.26 5360,3401.55 ; U1.4 5360,3401.55 ; P1.3 5400.8,3074.56 v1(5402,3075.76) ; C3.2 5377.28,3400.27 5376,3401.55 5360,3401.55
  Bottom Layer w6: SD1.4 2639.55,2758.31 ; v1(2655,2773.76) 2639.55,2758.31 ; v1(2870,2420.76) 2866,2424.76 2793.7,2424.76 C16.2 2793.7,2497.06 2729,2561.76 2729,2758.31 ; v1(2908,2158.76) 2908,2120.35 C1.2 3003,2120.35 3022.96,2140.31 3068,2140.31 ; U6.10 U6.10 3067,1980.76 ; C12.2 3240.1,1940.31 3208,1972.41 U6.1 3147,1972.41 3147,1980.76 3146,1981.76 3068,1981.76 3067,1980.76 ; C5.2 3273.74,2681.08 3279.5,2686.84 U8.3 3279.5,2857.15 3329.5,2907.15 3329.5,2939.76 ; U8.8 U8.7 3329.5,2939.76 ; U3.24 4012.5,3027.5 ; U3.9 3941.02,2666.76 3928.08,2653.82 3735.56,2653.82 3673.66,2591.92 C4.2 3674.66,2419.96 ; JP1.2 4080.45,3733.55 4073.66,3726.76 C2.2 4073.66,3532.76 4061.17,3520.27 R3.1 3713.71,3116.18 3700,3102.47 3253.71,3102.47 3028,2876.76 2750,2876.76 2734,2860.76 2734,2779.26 2713.05,2758.31 ; U3.36 4098.5,3041.76 4084.24,3027.5 4012.5,3027.5 ; U3.48 U3.48@4149.68,2810.76 ; v1(5110,3154.26) 5540.2,3154.26 5618.7,3075.76 ; U7.13 U7.13@5160,2626.41 ; U7.8 5273.27,2571.99 5287.5,2557.76 5500,2557.76 ; v1(5402,3075.76) 5618.7,3075.76 ; C17.2 C17.2@5513.71,2639.76 ; VCC.1 5533.7,2479.76 5513.71,2499.75 5513.71,2571.47 ; 2639.55,2758.31 2713.05,2758.31 ; 2713.05,2758.31 2729,2758.31 ; 2729,2758.31 2730.78,2756.54 2750,2775.76 ; 2729,2758.31 2750,2775.76 ; 2750,2775.76 2894,2775.76 2917,2798.76 3188.5,2798.76 3329.5,2939.76 ; 3067,1980.76 3067,2139.31 3068,2140.31 ; 3068,2140.31 C11.2 3247,2140.31 3526.45,2419.76 3674.66,2419.96 ; 3674.66,2419.96 4252,2420.76 ; 3674.66,2419.96 3674.66,2419.76 4252,2420.76 ; 4012.5,3027.5 4032,3008 4032,2828.76 4050,2810.76 U3.48@4149,2810.76 ; U3.48@4149,2810.76 U3.48@4149.68,2810.76 ; U3.48@4149,2810.76 4149,2705.76 4149.68,2705.08 ; 4149.68,2705.08 U3.48@4149.68,2810.76 ; 4149.68,2705.08 4252,2602.76 4252,2420.76 ; U3.48@4149.68,2810.76 4216,2810.76 4386.49,2640.27 C7.2 5100,2640.27 5113.86,2626.41 U7.13@5160,2626.41 ; U7.13@5160,2626.41 5160,2554.26 5185.31,2528.95 5471.19,2528.95 5500,2557.76 ; 5500,2557.76 5513.71,2571.47 ; 5513.71,2571.47 C17.2@5513.71,2639.76 ; C17.2@5513.71,2639.76 5619.19,2639.76 5633.69,2654.26 R19.1 5633.69,2849.76 R20.1 5633.7,3060.76 5618.7,3075.76
X1: C24.2 R23.1 U3.14 | length 1925.1
  Top Layer w6: v1(3959,2871.76) 4074,2871.76 4199,2746.76 4306.14,2746.76 4594,3034.62 v1(4594,3185.76)
  Bottom Layer w6: U3.14 3884.12,2830.65 3925.23,2871.76 v1(3959,2871.76) ; v1(4594,3185.76) 4623.69,3185.76 4636.69,3198.76 4639.68,3233.75 5233.68,3234.76 R23.1 5233.68,3329.76 ; 5233.71,3329.79 C24.2
X2: C26.2 R25.1 U3.13 | length 1179.5
  Top Layer w6: R25.1 2793,2660.31 ; 2793.02,2660.33 C26.2 v1(3499.57,2660.33)
  Bottom Layer w6: v1(3499.57,2660.33) 3647.75,2808.51 3756.99,2808.51 3759.44,2810.96 U3.13
Y1: C25.2 R22.1 U3.12 | length 2629.4
  Top Layer w6: v1(3831,2761.76) 3831,2929.26 3844.5,2942.76 4046,2942.76 4160,2828.76 4325,2828.76 4338,2841.76 4338,3191.76 4358,3211.76 4645.5,3211.76 v1(4658,3199.26)
  Bottom Layer w6: v1(3831,2761.76) 3881.96,2761.76 U3.12 ; v1(4658,3199.26) 4670.5,3211.76 5265,3211.76 5273,3219.76 5273,3304.26 5287.5,3318.76 5546,3318.76 5567,3297.76 5567,3281.31 5568,3280.31 R22.1 5593.72,3329.76 5593.68,3329.8 C25.2
Y2: C27.2 R24.1 U3.11 | length 1441.5
  Top Layer w6: C27.2 C27.2@2753.68,2442.15 ; R24.1 2753.72,2479.8 2753.68,2479.76 C27.2@2753.68,2442.15 ; v1(3480.39,2442.15) C27.2@2753.68,2442.15
  Bottom Layer w6: v1(3480.39,2442.15) 3712.3,2674.06 3887.5,2674.06 3901.65,2688.21 U3.11
pads on no net: JP1.0 P1.5 P1.6 P2.5 P2.6 SW1. U2.9 U6.0 U7.25 USB2.

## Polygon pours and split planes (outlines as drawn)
GND on Top Layer (solid): 1736.22,4137.79 5948.81,4137.79 5948.81,1500 1539.37,1539.37 1500,1736.22
GND on Bottom Layer (solid): 1736.22,4216.53 6066.92,4137.79 5988.18,1539.37 1617.51,1529.37

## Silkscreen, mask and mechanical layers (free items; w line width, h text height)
Bottom Overlay:
  lines w7.87: 3948.02,1820.05 cw(c3938.02,1820.16) 3948.02,1820.27 ; 3914.04,1761.24 3977.04,1761.24 4040.04,1761.24 4040.04,1800.24 4040.04,1839.24 3977.04,1839.24 3914.04,1839.24 3914.04,1800.24 3914.04,1761.24
  lines w10: 3383.7,3175.11 3483.7,3175.11 3483.7,3276.11 3383.7,3276.11 3383.7,3175.11 ; 3747.7,3380.11 3847.7,3380.11 3847.7,3481.11 3747.7,3481.11 3747.7,3380.11
  text "RESET" at 3896.7,3317.11 h45
  text "GND" at 3485.7,3115.11 h45
  text "Q2" at 3886.7,1734.11 h45
Document:
  lines w0.1: 3782.46,2857.26 3784.46,2859.26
